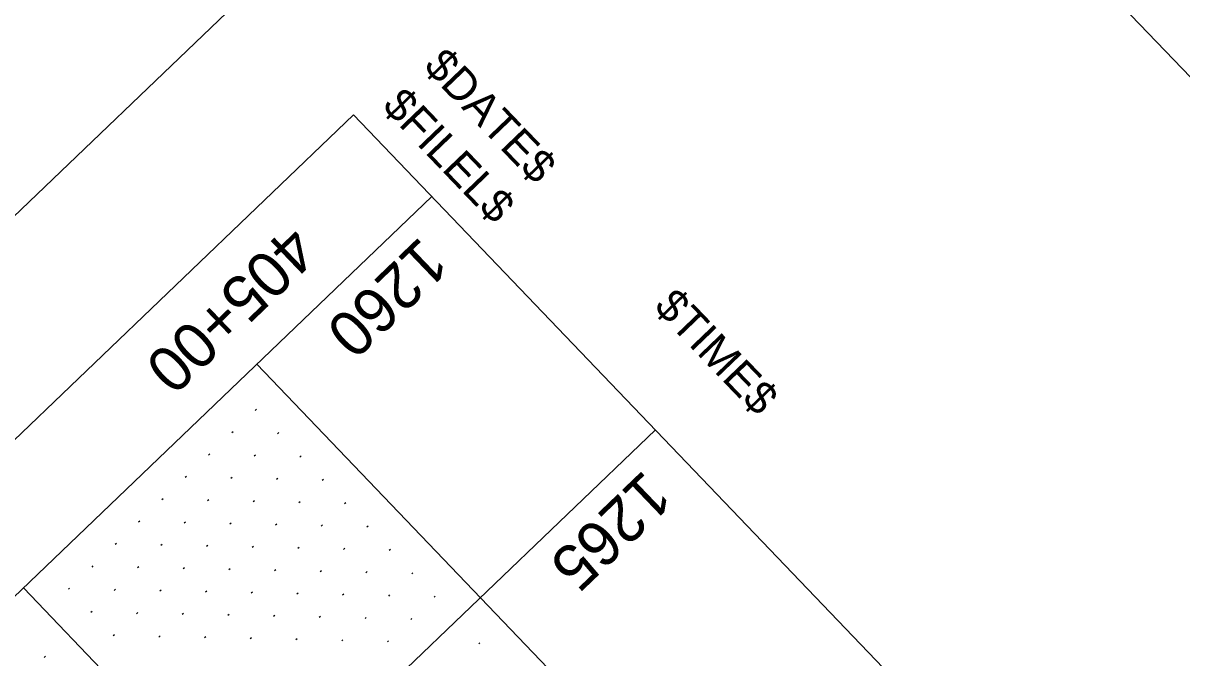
# Model space of a CAD drawing. Extents: x 2148987 to 2151117, y 142806 to 144993.
# Drawn here: x 2150164.2 to 2150343.4, y 144649 to 144747.2 of the extents above; entities that cross this region are included whole.
import ezdxf

# ---------------------------------------------------------------- set-up
doc = ezdxf.new("R2010")
doc.units = 0
for name, color, linetype in [('BASELINE', 7, 'Continuous'), ('Plan Notes', 7, 'Continuous'), ('PR_PIER_PH3', 7, 'Continuous'), ('PR_Road_Concrete', 7, 'Continuous'), ('SHT_Profile_Grid_Minor', 7, 'Continuous'), ('Wall D Bore', 7, 'Continuous'), ('Wall D Bore Txt', 7, 'Continuous')]:
    doc.layers.add(name, color=color, linetype=linetype)

msp = doc.modelspace()

# ---------------------------------------------------------------- linework, layer by layer
at = {"layer": 'BASELINE'}
msp.add_lwpolyline([(2151029.45, 144024.32), (2149802.07, 142848.08), (2149040.98, 143642.27), (2150268.36, 144818.51)], close=True, dxfattribs=at)
at = {"layer": 'PR_PIER_PH3'}
for p, q in [((2150261.97, 144684.26), (2149124.83, 143594.52)), ((2150164.2, 144659.82), (2150510.15, 144298.83))]:
    msp.add_line(p, q, dxfattribs=at)
at = {"layer": 'PR_Road_Concrete'}
for p, q in [((2150227.37, 144720.36), (2149279.76, 143812.24)), ((2150200.3, 144694.42), (2150546.25, 144333.42))]:
    msp.add_line(p, q, dxfattribs=at)
msp.add_lwpolyline([(2150941.76, 143974.91), (2149804.63, 142885.16), (2149078.13, 143643.25), (2150215.26, 144733)], close=True, dxfattribs=at)
at = {"layer": 'SHT_Profile_Grid_Minor'}
for p, q in [((2150200.24, 144687.43), (2150200.06, 144687.26)), ((2150196.63, 144683.97), (2150196.45, 144683.8)), ((2150203.7, 144683.82), (2150203.52, 144683.65)), ((2150193.02, 144680.52), (2150192.84, 144680.34)), ((2150200.09, 144680.36), (2150199.91, 144680.19)), ((2150207.16, 144680.21), (2150206.98, 144680.04)), ((2150189.41, 144677.06), (2150189.23, 144676.88)), ((2150196.48, 144676.91), (2150196.3, 144676.73)), ((2150203.55, 144676.75), (2150203.37, 144676.58)), ((2150210.62, 144676.6), (2150210.44, 144676.43)), ((2150185.8, 144673.6), (2150185.62, 144673.42)), ((2150192.87, 144673.45), (2150192.69, 144673.27)), ((2150199.94, 144673.3), (2150199.76, 144673.12)), ((2150207.01, 144673.14), (2150206.83, 144672.97)), ((2150214.08, 144672.99), (2150213.89, 144672.82)), ((2150182.19, 144670.14), (2150182.01, 144669.96)), ((2150189.26, 144669.99), (2150189.08, 144669.81)), ((2150196.33, 144669.84), (2150196.15, 144669.66)), ((2150203.4, 144669.69), (2150203.22, 144669.51)), ((2150210.47, 144669.54), (2150210.28, 144669.36)), ((2150217.53, 144669.38), (2150217.35, 144669.21)), ((2150178.58, 144666.68), (2150178.4, 144666.5)), ((2150185.65, 144666.53), (2150185.47, 144666.35)), ((2150192.72, 144666.38), (2150192.54, 144666.2)), ((2150199.79, 144666.23), (2150199.61, 144666.05)), ((2150206.86, 144666.08), (2150206.67, 144665.9)), ((2150213.92, 144665.93), (2150213.74, 144665.75)), ((2150220.99, 144665.77), (2150220.81, 144665.6)), ((2150174.97, 144663.22), (2150174.79, 144663.04)), ((2150182.04, 144663.07), (2150181.86, 144662.89)), ((2150189.11, 144662.92), (2150188.93, 144662.74)), ((2150196.18, 144662.77), (2150196, 144662.59)), ((2150203.25, 144662.62), (2150203.06, 144662.44)), ((2150210.31, 144662.47), (2150210.13, 144662.29)), ((2150217.38, 144662.32), (2150217.2, 144662.14)), ((2150224.45, 144662.16), (2150224.27, 144661.99)), ((2150171.36, 144659.76), (2150171.18, 144659.59)), ((2150178.43, 144659.61), (2150178.25, 144659.43)), ((2150185.5, 144659.46), (2150185.32, 144659.28)), ((2150192.57, 144659.31), (2150192.39, 144659.13)), ((2150199.64, 144659.16), (2150199.45, 144658.98)), ((2150206.7, 144659.01), (2150206.52, 144658.83)), ((2150213.77, 144658.86), (2150213.59, 144658.68)), ((2150220.84, 144658.71), (2150220.66, 144658.53)), ((2150227.91, 144658.55), (2150227.73, 144658.38)), ((2150174.82, 144656.15), (2150174.64, 144655.98)), ((2150181.89, 144656), (2150181.71, 144655.82)), ((2150188.96, 144655.85), (2150188.78, 144655.67)), ((2150196.03, 144655.7), (2150195.84, 144655.52)), ((2150203.09, 144655.55), (2150202.91, 144655.37)), ((2150210.16, 144655.4), (2150209.98, 144655.22)), ((2150217.23, 144655.25), (2150217.05, 144655.07)), ((2150224.3, 144655.1), (2150224.12, 144654.92)), ((2150178.28, 144652.54), (2150178.1, 144652.37)), ((2150185.35, 144652.39), (2150185.17, 144652.21)), ((2150192.42, 144652.24), (2150192.23, 144652.06)), ((2150199.48, 144652.09), (2150199.3, 144651.91)), ((2150206.55, 144651.94), (2150206.37, 144651.76)), ((2150213.62, 144651.79), (2150213.44, 144651.61)), ((2150220.69, 144651.64), (2150220.51, 144651.46)), ((2150234.83, 144651.33), (2150234.65, 144651.16)), ((2150167.6, 144649.23), (2150167.42, 144649.06))]:
    msp.add_line(p, q, dxfattribs=at)

# ---------------------------------------------------------------- texts
at = {"layer": 'Plan Notes'}
for s, p in [('$DATE$', (2150225.93, 144740.28)), ('$FILEL$', (2150219.52, 144734.14)), ('$TIME$', (2150261.56, 144703.1))]:
    msp.add_text(s, height=5, rotation=313.7809, dxfattribs=at).set_placement(p)
at = {"layer": 'Wall D Bore'}
for s, p in [('1260', (2150225.66, 144714.35)), ('1265', (2150260.26, 144678.25))]:
    msp.add_text(s, height=7, rotation=223.7809, dxfattribs=at).set_placement(p)
at = {"layer": 'Wall D Bore Txt'}
msp.add_text('405+00', height=7, rotation=223.7809, dxfattribs=at).set_placement((2150205.37, 144716.24))

doc.saveas('drawing.dxf')
